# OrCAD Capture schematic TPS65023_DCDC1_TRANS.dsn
size Custom; title: TPS65023x Power Management IC (PMIC) With 3 DC/DCs,; rev: 1.0; note: Datasheet: SLVS670L     EVM: SLVU193; note: Synchronous Step Down Converter
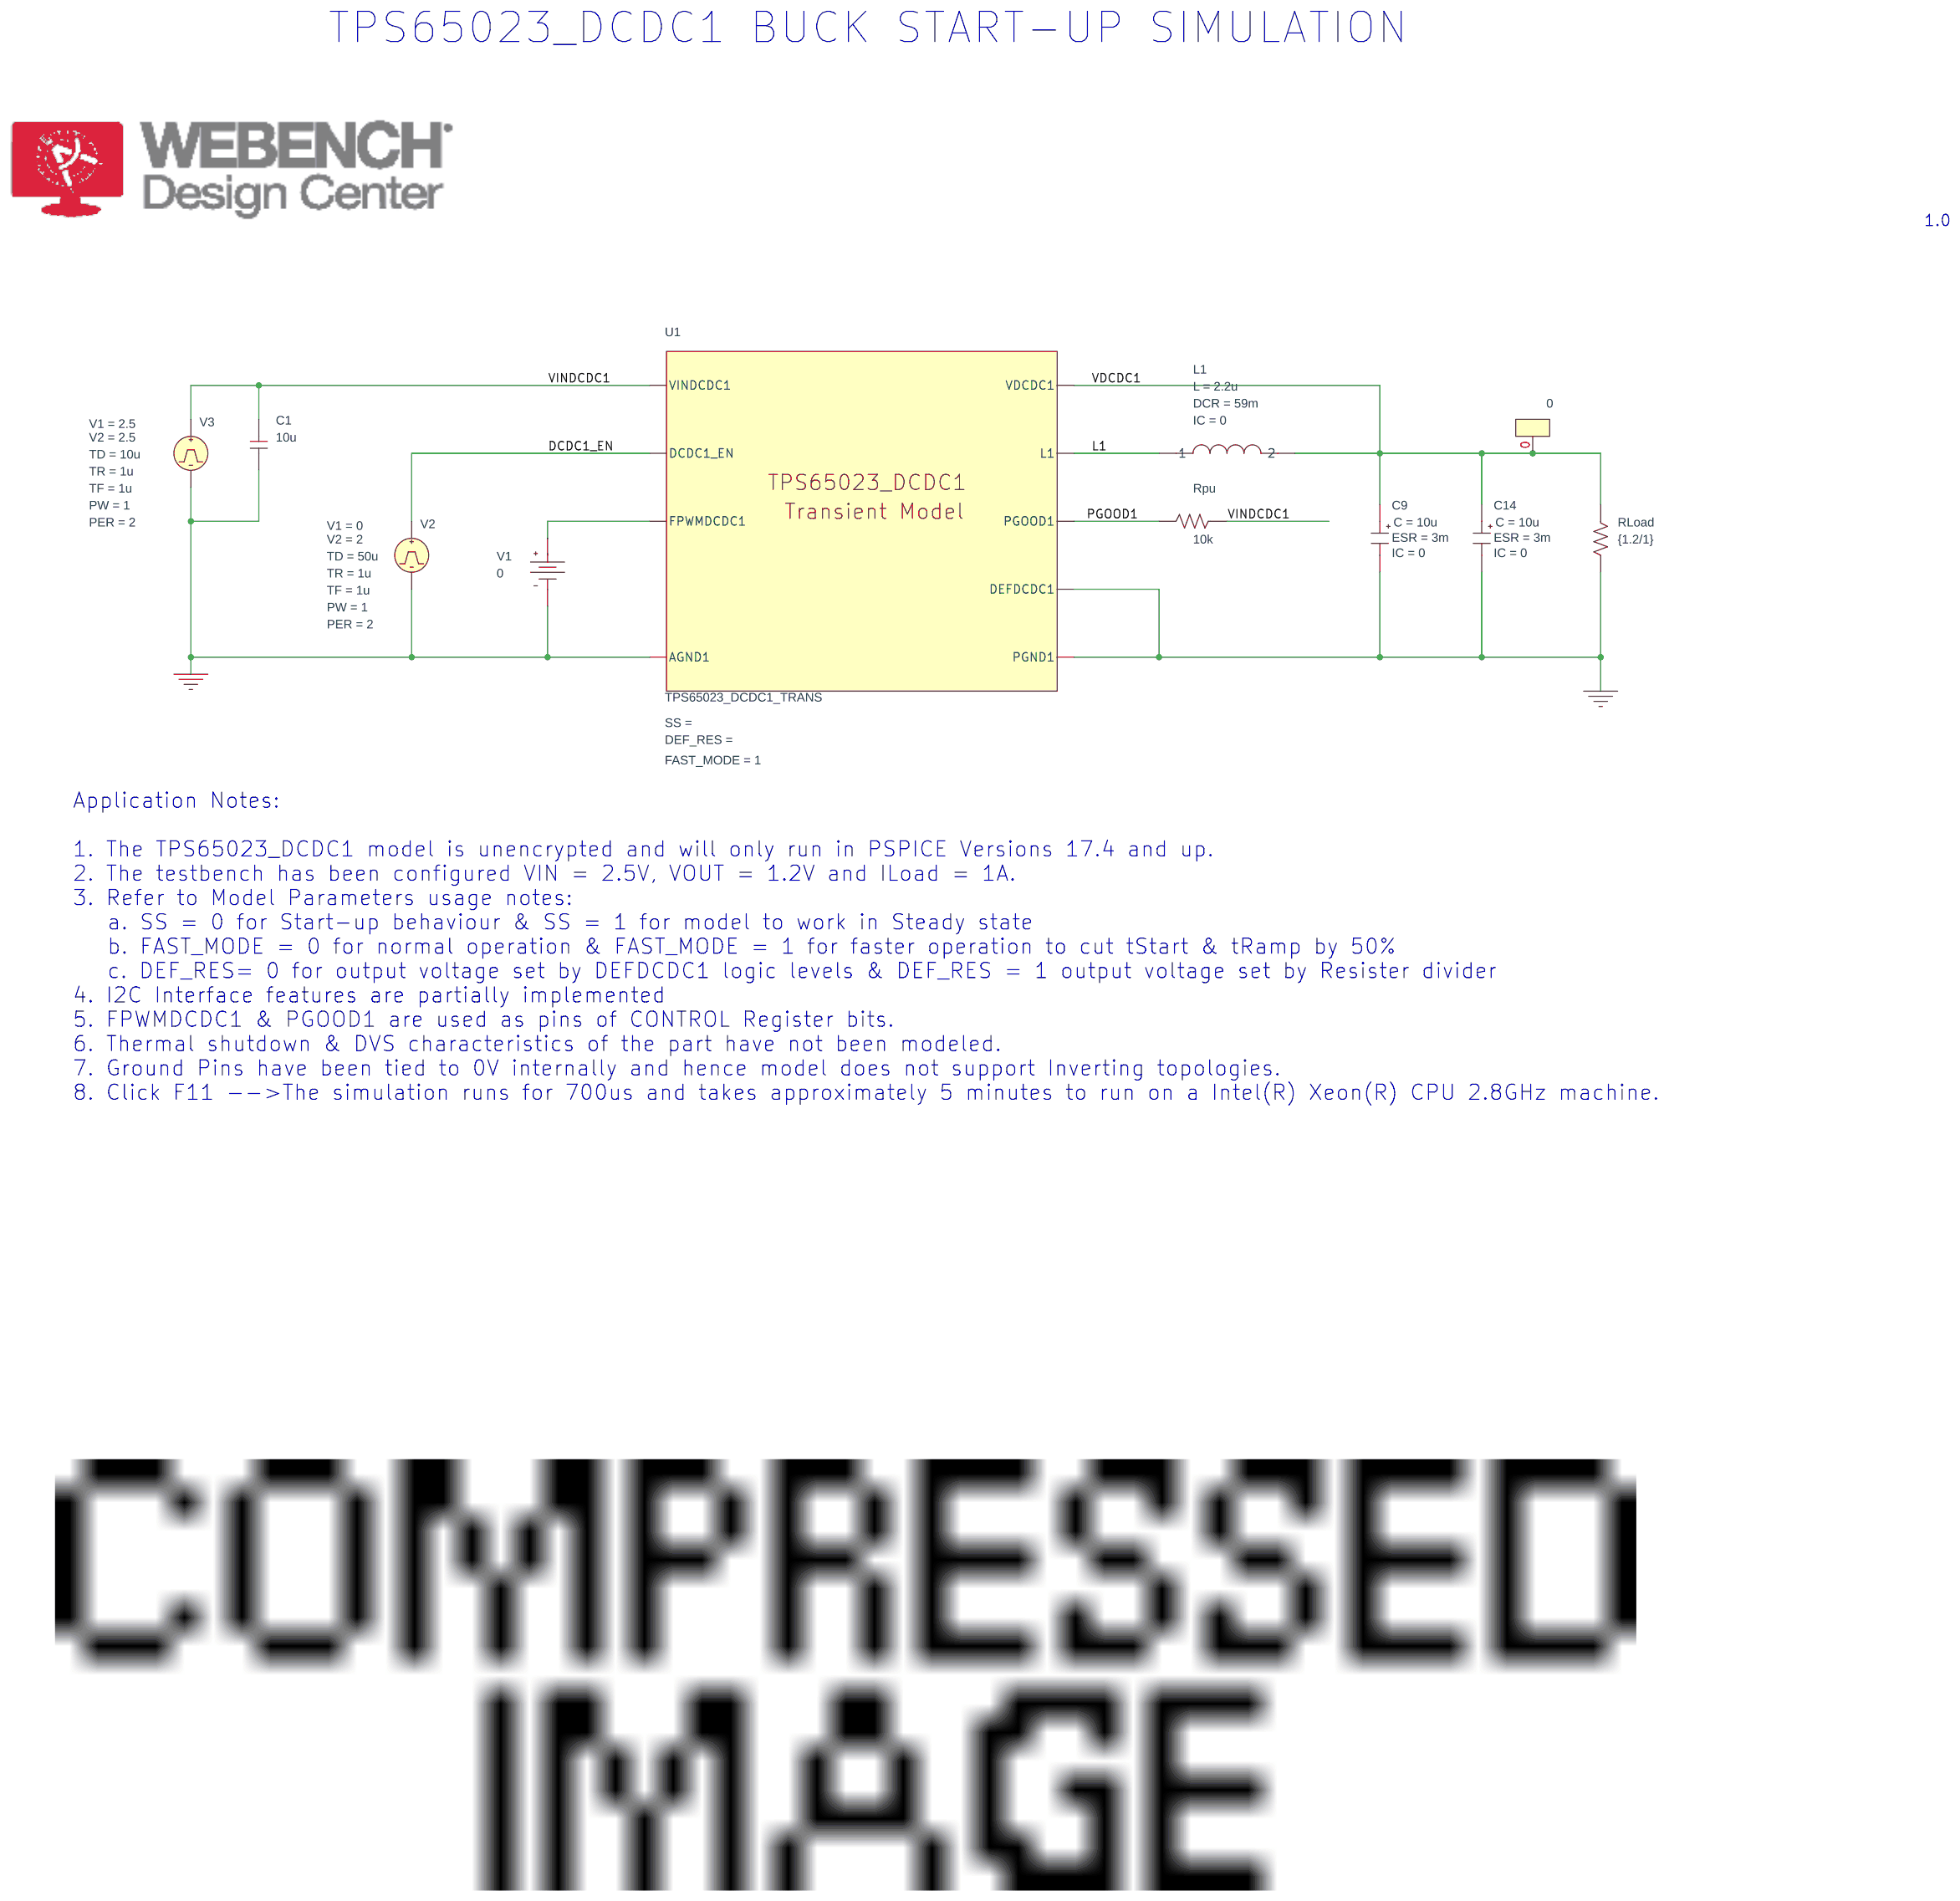
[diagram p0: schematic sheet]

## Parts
C1  10u  [RAD/CK05]
C9  CESR
C14  CESR
IC1  0
L1  LDCR
RLoad  {1.2/1}  [AX/RC05]
Rpu  10k  [AX/RC05]
U1  TPS65023_DCDC1_TRANS
V1  VDC
V2  VPULSE
V3  VPULSE

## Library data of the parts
C1 = C
C9 C14 = CESR_0: C: 10u; ESR: 3m; IC: 0; PSpiceTemplate: X^@REFDES %IN %OUT @MODEL PARAMS:  ?C|C=@C||C=100u|  ?ESR|ESR=@ESR||ESR=0.01| ?X|X=@X||X=2|  ?IC|IC=@IC||IC=2|; X: 1
IC1 = IC1
L1 = LDCR: DCR: 59m; IC: 0; L: 2.2u
RLoad Rpu = R
U1 = TPS65023_DCDC1_TRANS: FAST_MODE: 1
V1 = VDC: DC: 0
V2 = VPULSE: PER: 2; PW: 1; TD: 50u; TF: 1u; TR: 1u; V1: 0; V2: 2
V3 = VPULSE: PER: 2; PW: 1; TD: 10u; TF: 1u; TR: 1u; V1: 2.5; V2: 2.5

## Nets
VINDCDC1: C1.1 Rpu.1 U1.VINDCDC1 V3.1(+)
0: C1.2 C9.2(OUT) C14.2(OUT) RLoad.2 U1.AGND1 U1.DEFDCDC1 U1.PGND1 V1.1(-) V2.2(-) V3.2(-)
DCDC1_EN: U1.DCDC1_EN V2.1(+)
L1: L1.1 U1.L1
PGOOD1: Rpu.2 U1.PGOOD1
VDCDC1: C9.1(IN) C14.1(IN) IC1.0(+) L1.2 RLoad.1 U1.VDCDC1
N16775666: U1.FPWMDCDC1 V1.0(+)

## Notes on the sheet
- TPS65023_DCDC1 BUCK START-UP SIMULATION
- 1.0
- Application Notes:
  1. The TPS65023_DCDC1 model is unencrypted and will only run in PSPICE Versions 17.4 and up.
  2. The testbench has been configured VIN = 2.5V, VOUT = 1.2V and ILoad = 1A.
  3. Refer to Model Parameters usage notes:
     a. SS = 0 for Start-up behaviour & SS = 1 for model to work in Steady state
     b. FAST_MODE = 0 for normal operation & FAST_MODE = 1 for faster operation to cut tStart & tRamp by 50%
     c. DEF_RES= 0 for output voltage set by DEFDCDC1 logic levels & DEF_RES = 1 output voltage set by Resister divider
  4. I2C Interface features are partially implemented
  5. FPWMDCDC1 & PGOOD1 are used as pins of CONTROL Register bits.
  6. Thermal shutdown & DVS characteristics of the part have not been modeled.
  7. Ground Pins have been tied to 0V internally and hence model does not support Inverting topologies.
  8. Click F11 -->The simulation runs for 700us and takes approximately 5 minutes to run on a Intel(R) Xeon(R) CPU 2.8GHz machine.
